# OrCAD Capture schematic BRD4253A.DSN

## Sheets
1 02: RF, Antenna & Power: size A3; title: EFR32FG12 Dual Band 2400/915 MHz Radio Board; rev: A02; note: BRD4253A; note: TAB
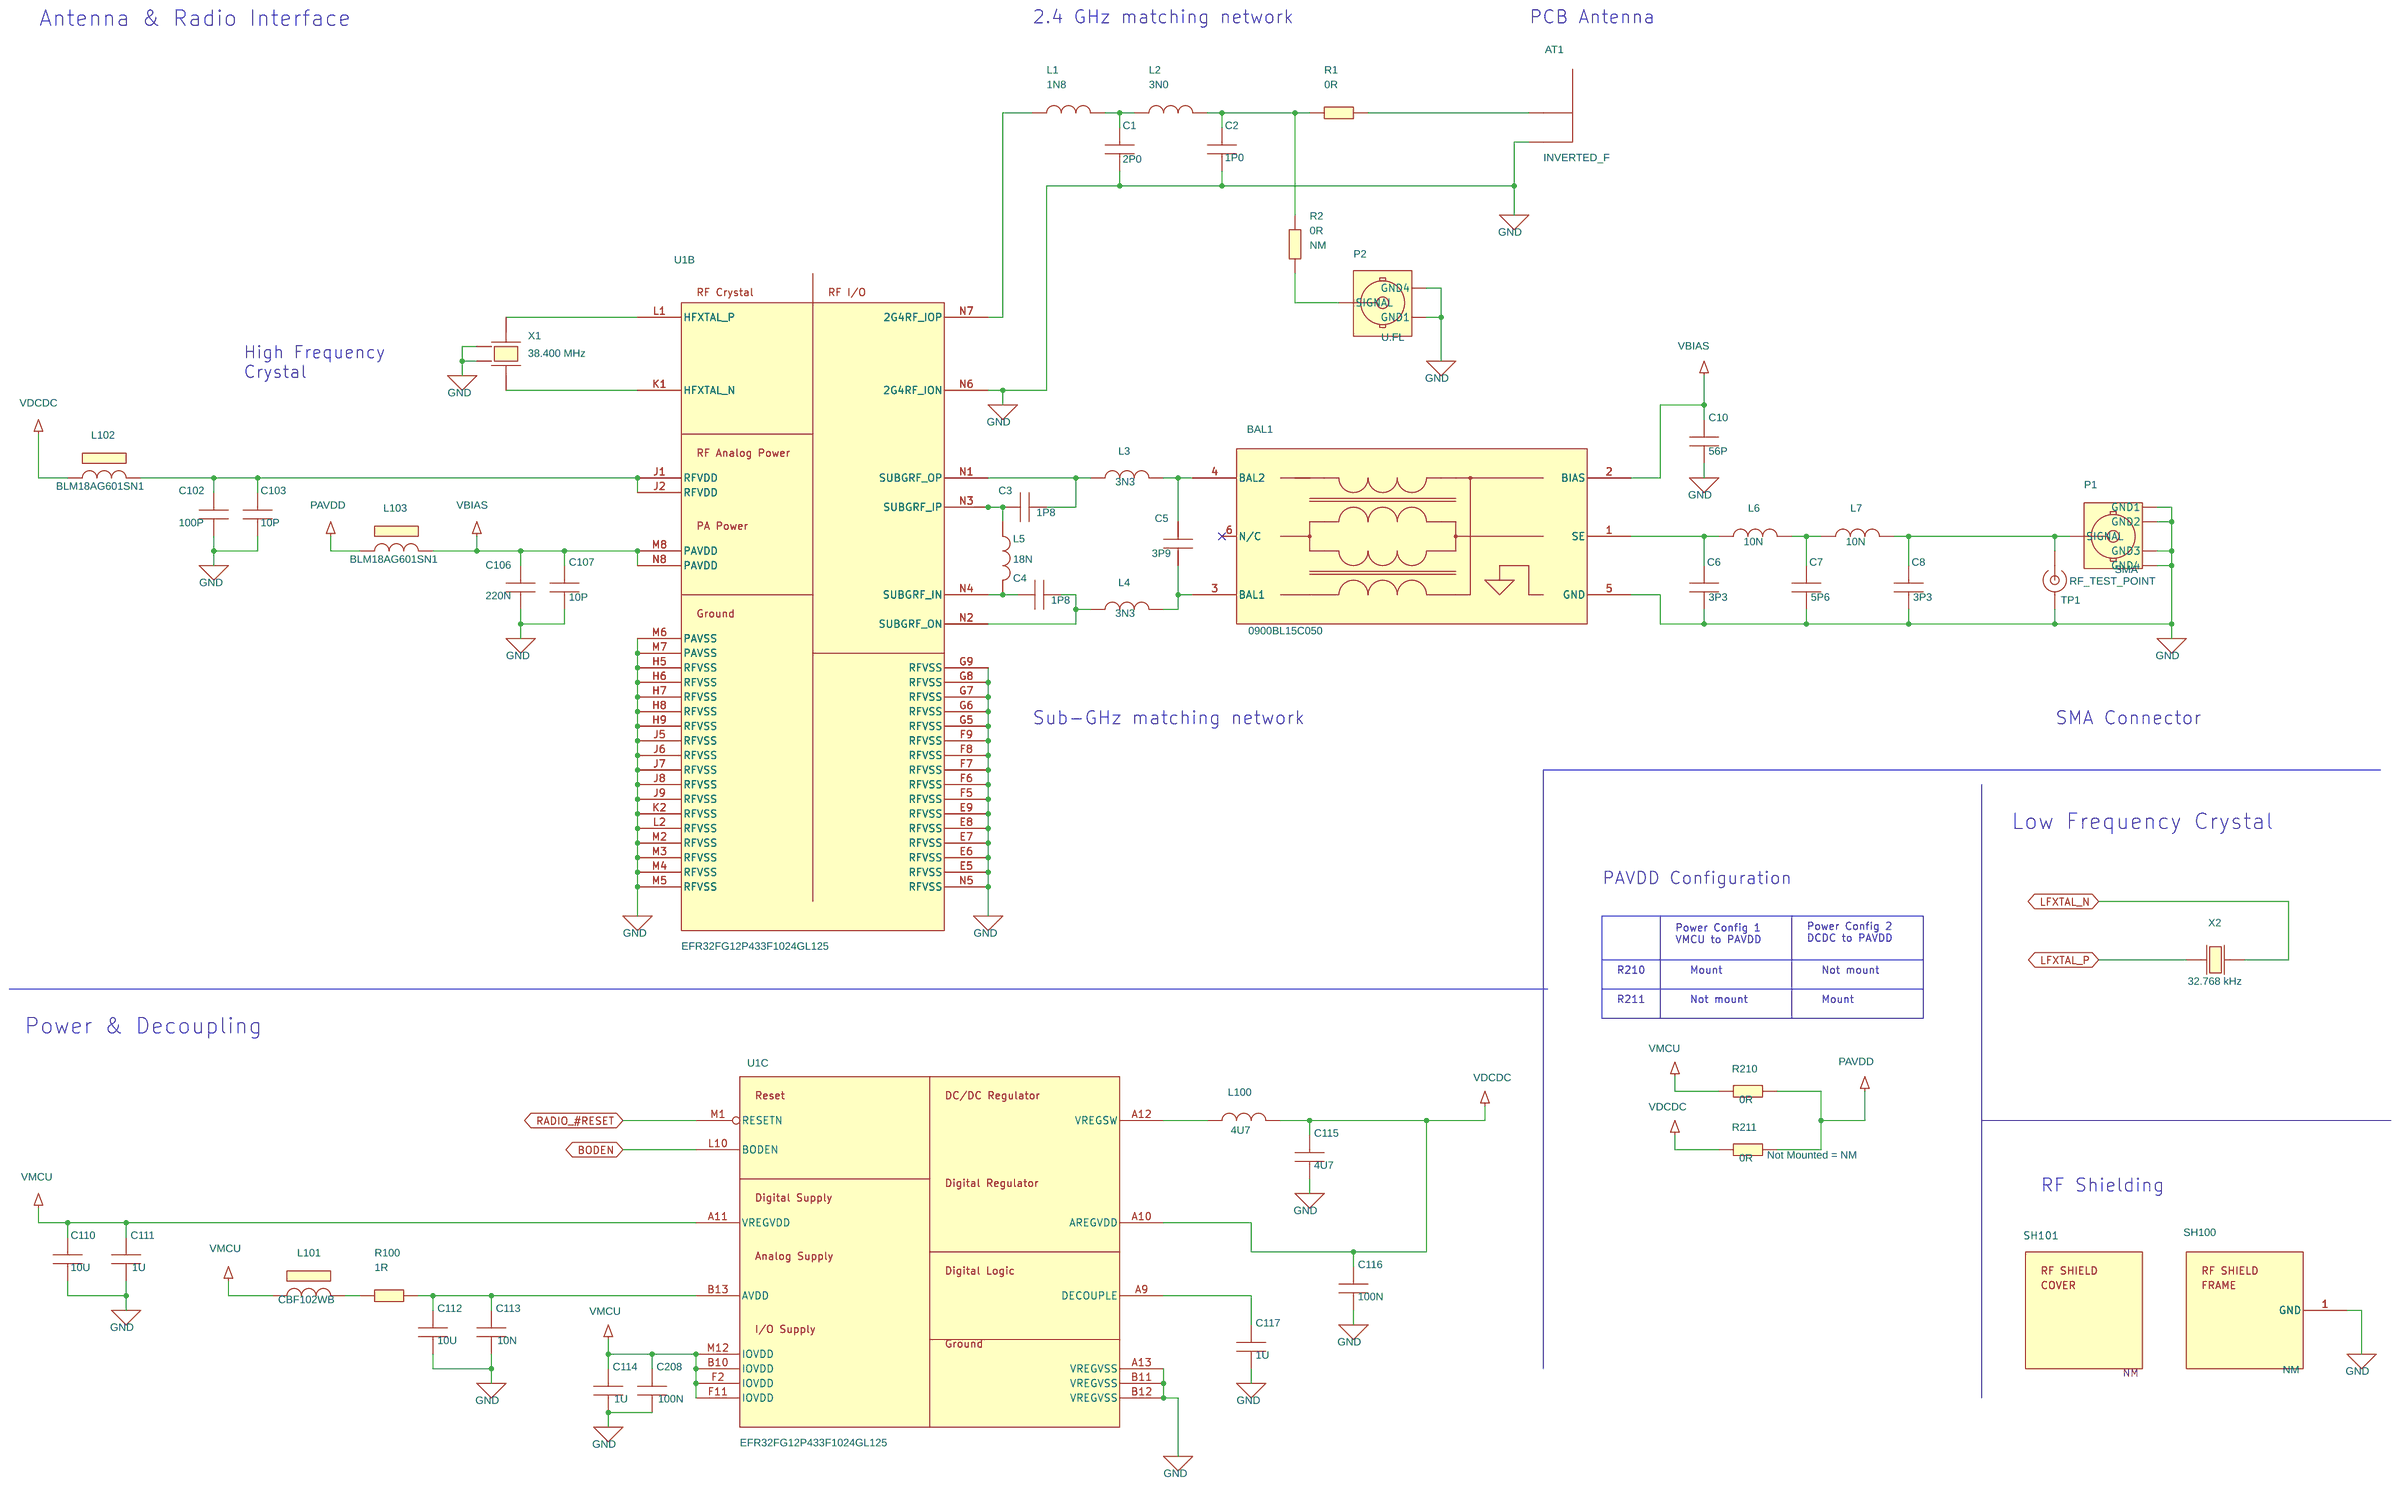
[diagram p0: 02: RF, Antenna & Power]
2 01: Title Page: company: Silicon Labs; note: JSH; note: JNO
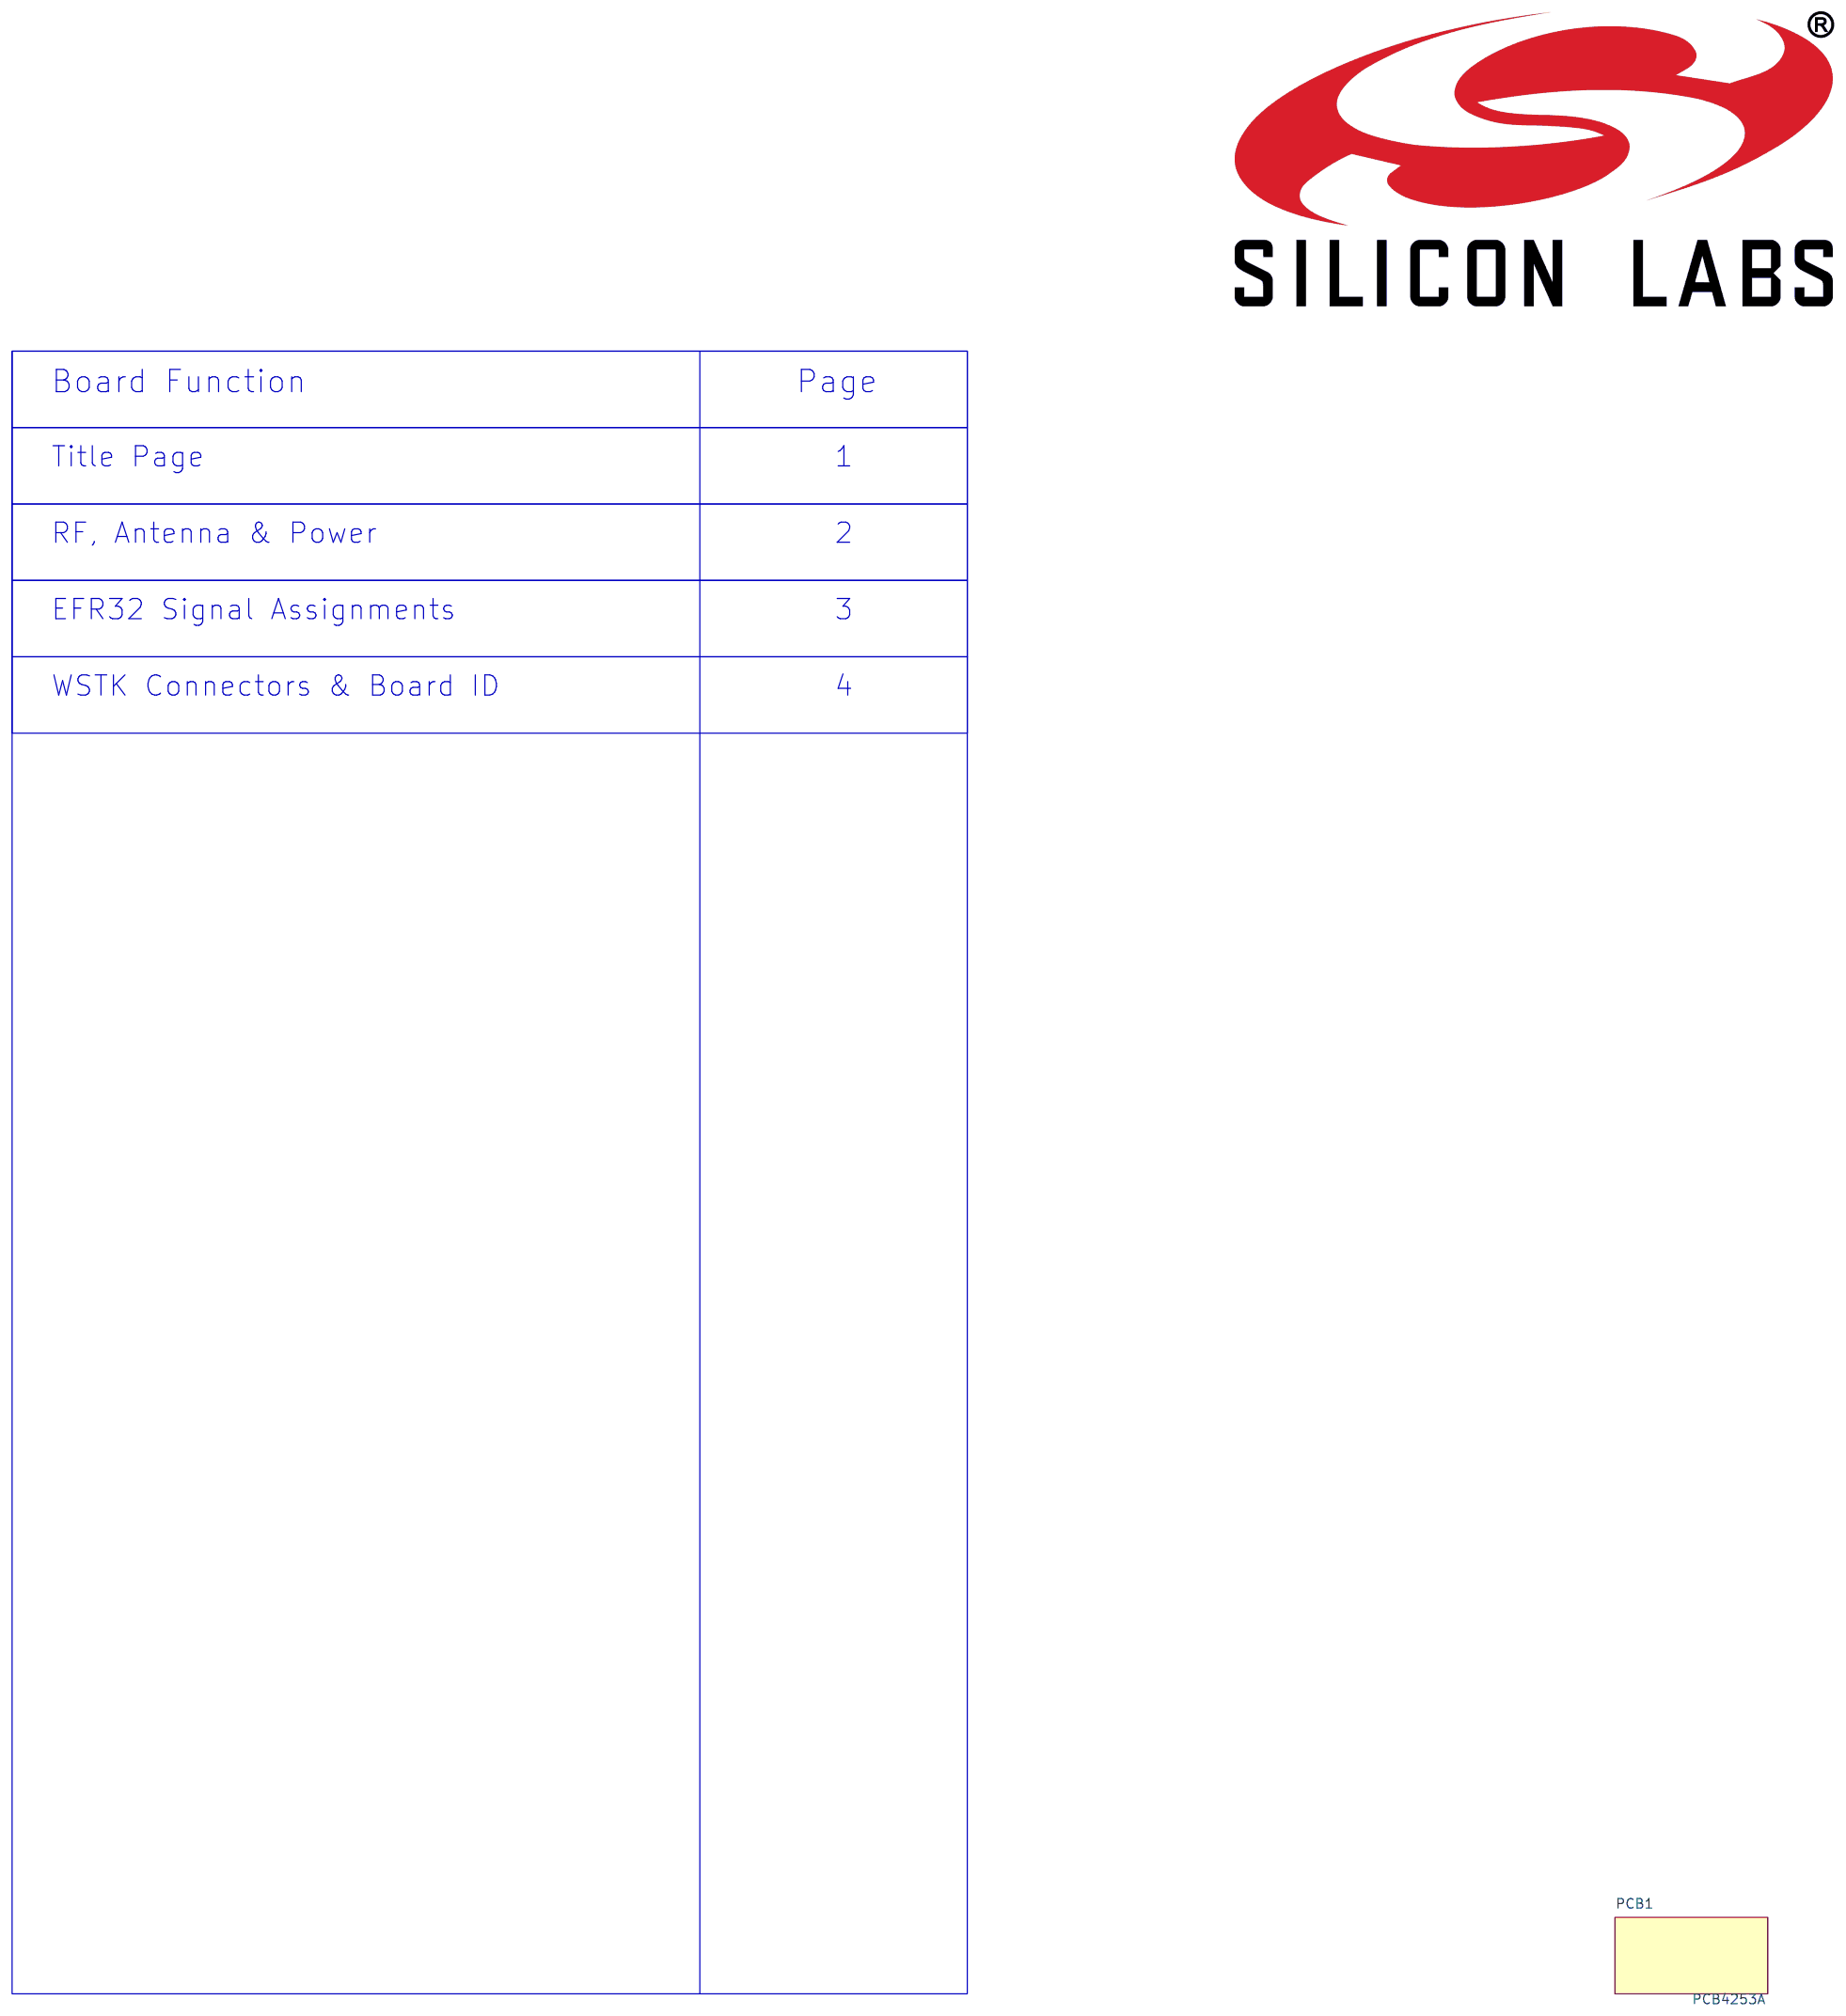
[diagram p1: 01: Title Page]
3 03: EFR32 Signal Assignments: size A3
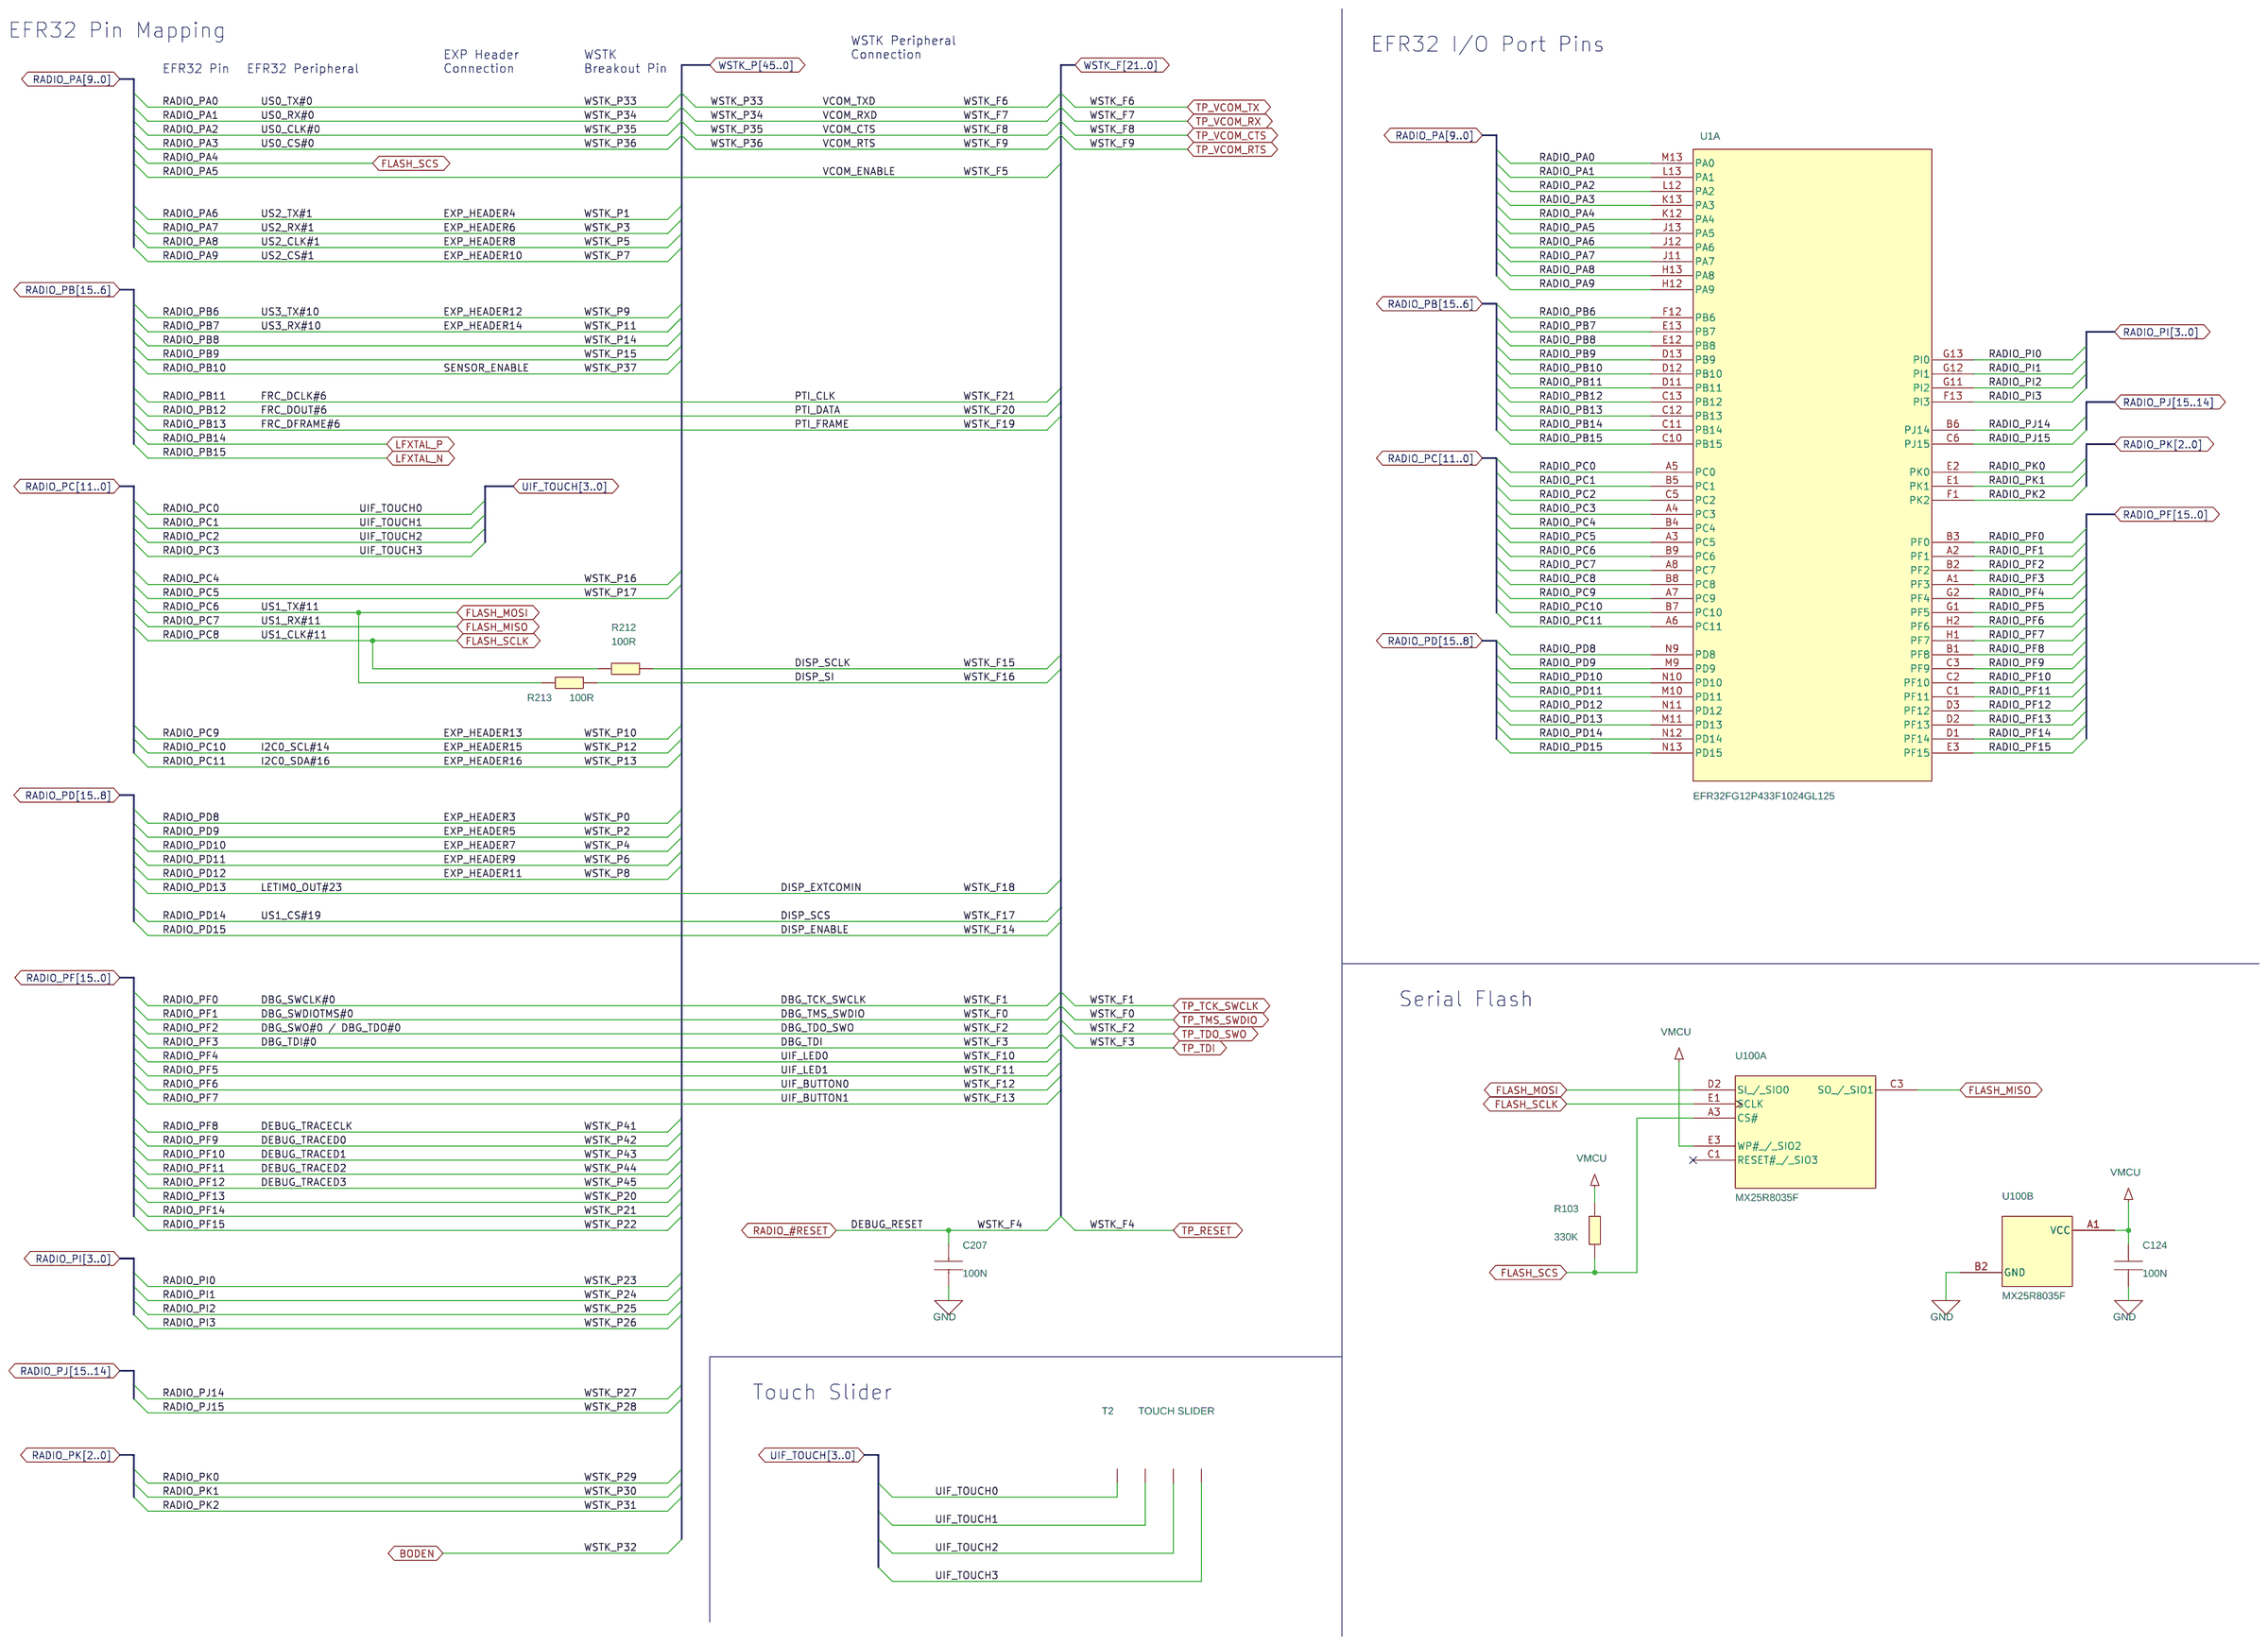
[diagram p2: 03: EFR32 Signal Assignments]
4 04: WSTK Connectors & Board ID: size A3
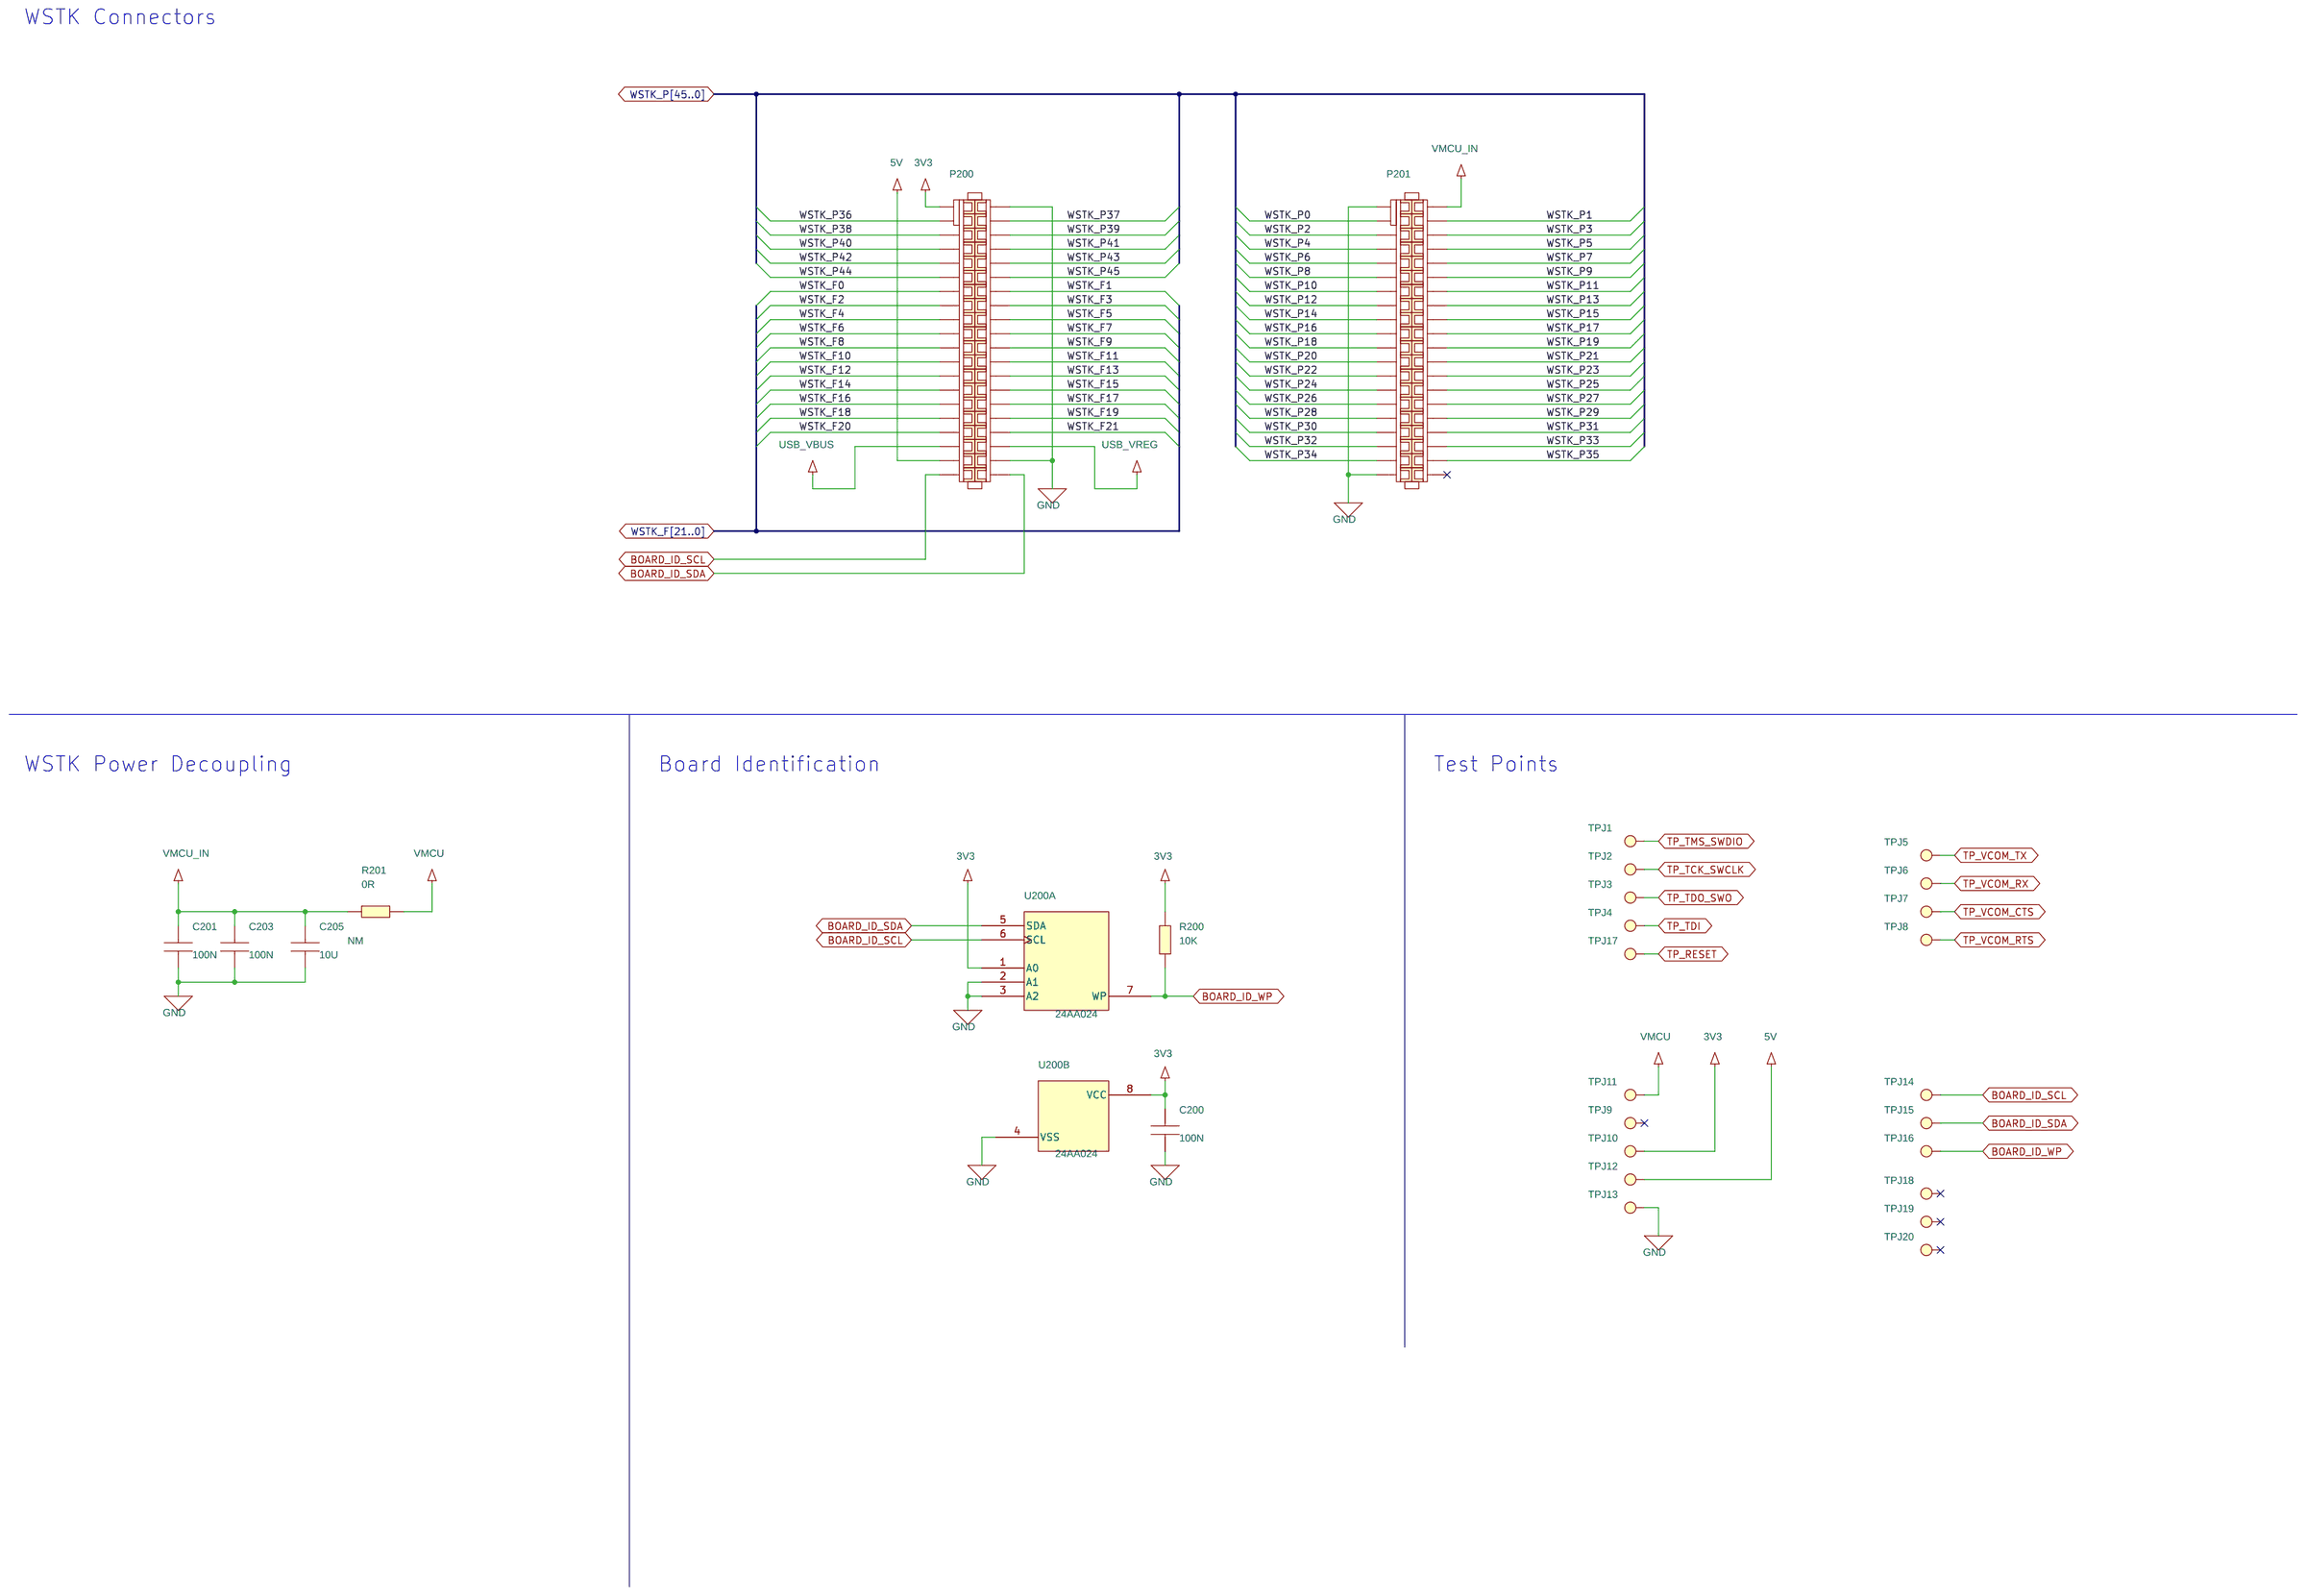
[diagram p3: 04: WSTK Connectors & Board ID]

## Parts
sheet 01: Title Page
PCB1  PCB4253A  [N/A]
sheet 02: RF, Antenna & Power
AT1  INVERTED_F  [ANT_INV_F_2.4_GHZ_17.3MM_MIR]
BAL1  0900BL15C050  [BALUN_JOH_0900BL15]
C1  2P0  [C0402_L]
C2  1P0  [C0402_L]
C3  1P8  [C0402_L]
C4  1P8  [C0402_L]
C5  3P9  [T_0402]
C6  3P3  [C0402_L]
C7  5P6  [C0402_L]
C8  3P3  [C0402_L]
C10  56P  [C0402_L]
C102  100P  [C0402_L]
C103  10P  [C0402_L]
C106  220N  [C0402_L]
C107  10P  [C0402_L]
C110  10U  [C0603_L]
C111  1U  [C0402_L]
C112  10U  [C0603_L]
C113  10N  [C0402_L]
C114  1U  [C0402_L]
C115  4U7  [C0402_L]
C116  100N  [C0402_L]
C117  1U  [C0402_L]
C208  100N  [C0402_L]
L1  1N8  [COIL_0402_L]
L2  3N0  [COIL_0402_L]
L3  3N3  [COIL_0402_L]
L4  3N3  [COIL_0402_L]
L5  18N  [COIL_0402_L]
L6  10N  [COIL_0402_L]
L7  10N  [COIL_0402_L]
L100  4U7  [COIL_MUR_LQH3NP_1212]
L101  CBF102WB  [COIL_WURTH_CBF_0603_L]
L102  BLM18AG601SN1  [COIL_MUR_BLM18_0603]
L103  BLM18AG601SN1  [COIL_MUR_BLM18_0603]
P1  SMA  [TE_SMA_1814832_TH_VER]
P2  U.FL  [COAX_HIROSE_U.FL_CL331-0471]
R1  0R  [R0402_L]
R2  0R  [R0402_L]
R100  1R  [R0402_L]
R210  0R  [R0402_L]
R211  0R  [R0402_L]
SH100  RF_SHIELD_FRAME_BMI-S-203-F  [RF_SHIELD_FRAME_BMI-S-203-F_PCB4100]
SH101  RF_SHIELD_COVER_BMI-S-203-C
TP1  RF_TEST_POINT  [TP_INGUN_50_OHM_CLOSED]
U1  EFR32FG12P433F1024GL125  (sections A,B,C)
X1  38.400 MHz  [X_SSS_DSX211SH_2.05X1.65-4]
X2  32.768 kHz  [X_MCS_CM8V-T1A]
sheet 03: EFR32 Signal Assignments
C124  100N  [C0402_L]
C207  100N  [C0402_L]
R103  330K  [R0402_L]
R212  100R  [R0402_L]
R213  100R  [R0402_L]
T2  TOUCH SLIDER  [TOUCH_SLIDER2_28.0X7.0-4]
U100  MX25R8035F  [BGA8_M040_1.24x1.75_WLCSP]  (sections A,B)
sheet 04: WSTK Connectors & Board ID
C200  100N  [C0402_L]
C201  100N  [C0402_L]
C203  100N  [C0402_L]
C205  10U  [C0805_L]
P200  SOCKET_2X20_1.27MM_SMD  [SAM_SFC-120-T2-D-A-2X20_SNUM]
P201  SOCKET_2X20_1.27MM_SMD  [SAM_SFC-120-T2-D-A-2X20_SNUM]
R200  10K  [T_0402]
R201  0R  [R0402_L]
TPJ1  TPJ_SMD  [TP_1.0_SMD]
TPJ2  TPJ_SMD  [TP_1.0_SMD]
TPJ3  TPJ_SMD  [TP_1.0_SMD]
TPJ4  TPJ_SMD  [TP_1.0_SMD]
TPJ5  TPJ_SMD  [TP_1.0_SMD]
TPJ6  TPJ_SMD  [TP_1.0_SMD]
TPJ7  TPJ_SMD  [TP_1.0_SMD]
TPJ8  TPJ_SMD  [TP_1.0_SMD]
TPJ9  TPJ_SMD  [TP_1.0_SMD]
TPJ10  TPJ_SMD  [TP_1.0_SMD]
TPJ11  TPJ_SMD  [TP_1.0_SMD]
TPJ12  TPJ_SMD  [TP_1.0_SMD]
TPJ13  TPJ_SMD  [TP_1.0_SMD]
TPJ14  TPJ_SMD  [TP_1.0_SMD]
TPJ15  TPJ_SMD  [TP_1.0_SMD]
TPJ16  TPJ_SMD  [TP_1.0_SMD]
TPJ17  TPJ_SMD  [TP_1.0_SMD]
TPJ18  TPJ_SMD  [TP_1.0_SMD]
TPJ19  TPJ_SMD  [TP_1.0_SMD]
TPJ20  TPJ_SMD  [TP_1.0_SMD]
U200  24AA024  [TDFN8_M050_2.0X3.0_EP]  (sections A,B)

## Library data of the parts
PCB1 = PCB: Mfg #: PCB4253A Rev. A01
AT1 = ANT_INVERTED_F
BAL1 = 0900BL15C050: Mfg: Johanson Technology
C1 = C0402: Mfg: Murata; Mfg #: GRM1555C1H2R0WA01D; Technology: C0G; Tolerance: ±0.05P
C2 = C0402: Mfg: Murata; Mfg #: GRM1555C1H1R0WA01D; Technology: C0G; Tolerance: ±0.05P
C3 C4 = C0402: Mfg: Murata; Mfg #: GRM1555C1H1R8WA01D; Technology: C0G; Tolerance: ±0.05pF
C5 = C0402: Mfg: Murata; Mfg #: GRM1555C1H3R9WA01D; Technology: C0G; Tolerance: ±0.05pF
C6 C8 = C0402: Mfg: Murata; Mfg #: GRM1555C1H3R3BA01D; Technology: C0G; Tolerance: ±0.1pF
C7 = C0402: Mfg: Murata; Mfg #: GRM1555C1H5R6BA01D; Technology: C0G; Tolerance: ±0.1pF
C10 = C0402: Mfg: Murata; Mfg #: GRM1555C1H560GA01D; Technology: C0G; Tolerance: ±2%
C102 C103 C107 = C0402: Rating: 50V; Technology: C0G; Tolerance: 5%
C106 C113 C116 C124 C200 C201 C203 C207 = C0402: Rating: 16V; Technology: X7R; Tolerance: 10%
C110 C112 = C0603: Rating: 6.3V; Technology: X5R; Tolerance: 20%
C111 C114 C117 C208 = C0402: Rating: 25V; Technology: X5R; Tolerance: 10%
C115 = C0402: Rating: 6.3V; Technology: X5R; Tolerance: 10%
L1 = L0402: Mfg: Murata; Mfg #: LQP15MN1N8W02D; Tolerance: ±0.05N
L2 = L0402: Mfg: Murata; Mfg #: LQP15MN3N0W02D; Tolerance: ±0.05N
L3 L4 = L0402: Mfg: Murata; Mfg #: LQW15AN3N3B80D; Tolerance: ±0.1nH
L5 = L0402: Mfg: Murata; Mfg #: LQW15AN18NG00D; Tolerance: ±2%
L6 L7 = L0402: Mfg: Murata; Mfg #: LQW15AN10NJ00D; Tolerance: ±5%
L100 = LQH3NP: Mfg #: LQH3NPN4R7MM0L
L101 = CBF102WB
L102 L103 = BLM18AG
P1 = SMA_TH
P2 = HIROSE_U.FL
R1 R100 R103 R200 R201 R210 R212 R213 = R0402
R2 R211 = R0402: Not Mounted: NM
SH100 = RF_SHIELD_FRAME_BMI-S-203-F: Not Mounted: NM
SH101 = RF_SHIELD_COVER_BMI-S-203-C: Not Mounted: NM
TP1 = TP_RF
U1 = EFR32MG2_BGA125_0A: Mfg #: EFR32FG12P433F1024GL125-BR
X1 = DSX211SH: Mfg: KDS; Mfg #: DSX211SH 1ZZNAE38400AB0A
X2 = CM8V-T1A: Mfg: KDS; Mfg #: DST210 1TJG125DP1A0012
T2 = TOUCH_SLIDER: CONTEC Footprint: TOUCH_SLIDER_28.0X7.0-4_L111
U100 = MX25R8035
C205 = C0805: Not Mounted: NM; Rating: 10V; Technology: X5R; Tolerance: 10%
P200 P201 = SOCKET_2X20_1.27MM_SMD
TPJ1-TPJ20 = TPJ_SMD
U200 = 24AA024

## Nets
3V3: C200.1 P200.1 R200.2 TPJ10.1(TP) U200.1(A0) U200.8(VCC)
5V: P200.37 TPJ12.1(TP)
GND: AT1.2(GND) BAL1.5(GND) C1.1 C2.1 C6.2 C7.2 C8.2 C10.2 C102.2 C103.2 C106.2 C107.2 C110.2 C111.2 C112.2 C113.2 C114.2 C115.2 C116.2 C117.2 C124.2 C200.2 C201.2 C203.2 C205.2 C207.2 C208.2 P1.2(GND1) P1.3(GND2) P1.4(GND3) P1.5(GND4) P2.2(GND1) P2.3(GND4) P200.2 P200.38 P201.1 P201.39 SH100.1(GND) TP1.2(GND) TPJ13.1(TP) U1.A13(VREGVSS) U1.B11(VREGVSS) U1.B12(VREGVSS) U1.E5(RFVSS) U1.E6(RFVSS) U1.E7(RFVSS) U1.E8(RFVSS) U1.E9(RFVSS) U1.F5(RFVSS) U1.F6(RFVSS) U1.F7(RFVSS) U1.F8(RFVSS) U1.F9(RFVSS) U1.G5(RFVSS) U1.G6(RFVSS) U1.G7(RFVSS) U1.G8(RFVSS) U1.G9(RFVSS) U1.H5(RFVSS) U1.H6(RFVSS) U1.H7(RFVSS) U1.H8(RFVSS) U1.H9(RFVSS) U1.J5(RFVSS) U1.J6(RFVSS) U1.J7(RFVSS) U1.J8(RFVSS) U1.J9(RFVSS) U1.K2(RFVSS) U1.L2(RFVSS) U1.M2(RFVSS) U1.M3(RFVSS) U1.M4(RFVSS) U1.M5(RFVSS) U1.M6(PAVSS) U1.M7(PAVSS) U1.N5(RFVSS) U1.N6(2G4RF_ION) U100.B2(GND) U200.2(A1) U200.3(A2) U200.4(VSS) X1.2 X1.4
BOARD_ID_SCL: P200.39 TPJ14.1(TP) U200.6(SCL)
BOARD_ID_SDA: P200.40 TPJ15.1(TP) U200.5(SDA)
BOARD_ID_WP: R200.1 TPJ16.1(TP) U200.7(WP)
BODEN: P201.35 U1.L10(BODEN)
FLASH_MISO: U1.A8(PC7) U100.C3(SO_/_SIO1)
FLASH_MOSI: R213.1 U1.B9(PC6) U100.D2(SI_/_SIO0)
FLASH_SCLK: R212.1 U1.B8(PC8) U100.E1(SCLK)
FLASH_SCS: R103.2 U1.K12(PA4) U100.A3(CS#)
LFXTAL_N: U1.C10(PB15) X2.1
LFXTAL_P: U1.C11(PB14) X2.2
PAVDD: L103.1 R210.1 R211.1
RADIO_#RESET: C207.1 P200.17 TPJ17.1(TP) U1.M1(RESETN)
RADIO_PA0: P200.19 P201.36 TPJ5.1(TP) U1.M13(PA0)
RADIO_PA1: P200.20 P201.37 TPJ6.1(TP) U1.L13(PA1)
RADIO_PA2: P200.21 P201.38 TPJ7.1(TP) U1.L12(PA2)
RADIO_PA3: P200.3 P200.22 TPJ8.1(TP) U1.K13(PA3)
RADIO_PA5: P200.18 U1.J13(PA5)
RADIO_PA6: P201.4 U1.J12(PA6)
RADIO_PA7: P201.6 U1.J11(PA7)
RADIO_PA8: P201.8 U1.H13(PA8)
RADIO_PA9: P201.10 U1.H12(PA9)
RADIO_PB6: P201.12 U1.F12(PB6)
RADIO_PB7: P201.14 U1.E13(PB7)
RADIO_PB8: P201.17 U1.E12(PB8)
RADIO_PB9: P201.18 U1.D13(PB9)
RADIO_PB10: P200.4 U1.D12(PB10)
RADIO_PB11: P200.34 U1.D11(PB11)
RADIO_PB12: P200.33 U1.C13(PB12)
RADIO_PB13: P200.32 U1.C12(PB13)
RADIO_PC0: T2.1(S1) U1.A5(PC0)
RADIO_PC1: T2.2(S2) U1.B5(PC1)
RADIO_PC2: T2.3(S3) U1.C5(PC2)
RADIO_PC3: T2.4(S4) U1.A4(PC3)
RADIO_PC4: P201.19 U1.B4(PC4)
RADIO_PC5: P201.20 U1.A3(PC5)
RADIO_PC9: P201.13 U1.A7(PC9)
RADIO_PC10: P201.15 U1.B7(PC10)
RADIO_PC11: P201.16 U1.A6(PC11)
RADIO_PD8: P201.3 U1.N9(PD8)
RADIO_PD9: P201.5 U1.M9(PD9)
RADIO_PD10: P201.7 U1.N10(PD10)
RADIO_PD11: P201.9 U1.M10(PD11)
RADIO_PD12: P201.11 U1.N11(PD12)
RADIO_PD13: P200.31 U1.M11(PD13)
RADIO_PD14: P200.30 U1.N12(PD14)
RADIO_PD15: P200.27 U1.N13(PD15)
RADIO_PF0: P200.14 TPJ2.1(TP) U1.B3(PF0)
RADIO_PF1: P200.13 TPJ1.1(TP) U1.A2(PF1)
RADIO_PF2: P200.15 TPJ3.1(TP) U1.B2(PF2)
RADIO_PF3: P200.16 TPJ4.1(TP) U1.A1(PF3)
RADIO_PF4: P200.23 U1.G2(PF4)
RADIO_PF5: P200.24 U1.G1(PF5)
RADIO_PF6: P200.25 U1.H2(PF6)
RADIO_PF7: P200.26 U1.H1(PF7)
RADIO_PF8: P200.8 U1.B1(PF8)
RADIO_PF9: P200.9 U1.C3(PF9)
RADIO_PF10: P200.10 U1.C2(PF10)
RADIO_PF11: P200.11 U1.C1(PF11)
RADIO_PF12: P200.12 U1.D3(PF12)
RADIO_PF13: P201.23 U1.D2(PF13)
RADIO_PF14: P201.24 U1.D1(PF14)
RADIO_PF15: P201.25 U1.E3(PF15)
RADIO_PI0: P201.26 U1.G13(PI0)
RADIO_PI1: P201.27 U1.G12(PI1)
RADIO_PI2: P201.28 U1.G11(PI2)
RADIO_PI3: P201.29 U1.F13(PI3)
RADIO_PJ14: P201.30 U1.B6(PJ14)
RADIO_PJ15: P201.31 U1.C6(PJ15)
RADIO_PK0: P201.32 U1.E2(PK0)
RADIO_PK1: P201.33 U1.E1(PK1)
RADIO_PK2: P201.34 U1.F1(PK2)
USB_VBUS: P200.35
USB_VREG: P200.36
VBIAS: BAL1.2(BIAS) C10.1 C106.1 C107.1 L103.2 U1.M8(PAVDD) U1.N8(PAVDD)
VDCDC: C115.1 C116.1 L100.2 L102.1 R211.2 U1.A10(AREGVDD)
VMCU: C110.1 C111.1 C114.1 C124.1 C208.1 L101.1 R103.1 R201.2 R210.2 TPJ11.1(TP) U1.A11(VREGVDD) U1.B10(IOVDD) U1.F2(IOVDD) U1.F11(IOVDD) U1.M12(IOVDD) U100.A1(VCC) U100.E3(WP#_/_SIO2)
VMCU_IN: C201.1 C203.1 C205.1 P201.2 R201.1
WSTK_F15: P200.28 R212.2
WSTK_F16: P200.29 R213.2
WSTK_P18: P201.21
WSTK_P19: P201.22
WSTK_P38: P200.5
WSTK_P39: P200.6
WSTK_P40: P200.7
N17603239: L1.1 U1.N7(2G4RF_IOP)
N17603622: U1.K1(HFXTAL_N) X1.1
N17603629: U1.L1(HFXTAL_P) X1.3
N17633617: C3.2 L5.2 U1.N3(SUBGRF_IP)
N17633620: C4.2 L5.1 U1.N4(SUBGRF_IN)
N17635927: C3.1 L3.2 U1.N1(SUBGRF_OP)
N17635932: C4.1 L4.2 U1.N2(SUBGRF_ON)
N17636016: BAL1.4(BAL2) C5.1 L3.1
N17636021: BAL1.3(BAL1) C5.2 L4.1
N17636973: C8.1 L7.1 P1.1(SIGNAL) TP1.1(RF)
N17636997: C7.1 L6.1 L7.2
N17637007: BAL1.1(SE) C6.1 L6.2
N17769146: C117.1 U1.A9(DECOUPLE)
N17769405: L100.1 U1.A12(VREGSW)
N17853356: C102.1 C103.1 L102.2 U1.J1(RFVDD) U1.J2(RFVDD)
N17855293: C2.2 L2.2 R1.1 R2.1
N17855333: P2.1(SIGNAL) R2.2
N17855346: AT1.1(ANT) R1.2
N17855379: C1.2 L1.2 L2.1
N17857389: L101.2 R100.1
N17857391: C112.1 C113.1 R100.2 U1.B13(AVDD)

Not connected (* = marked no-connect by the designer): BAL1 6(N/C)*; P201 40*; TPJ9 1(TP)*; TPJ18 1(TP)*; TPJ19 1(TP)*; TPJ20 1(TP)*; U100 C1(RESET#_/_SIO3)*

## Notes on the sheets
sheet 1
- Antenna & Radio Interface
- 2.4 GHz matching network
- PCB Antenna
- High Frequency
  Crystal
- Sub-GHz matching network
- SMA Connector
- Low Frequency Crystal
- PAVDD Configuration
- Power Config 1
  VMCU to PAVDD
- Power Config 2
  DCDC to PAVDD
- R210
- Mount
- Not mount
- R211
- Not mount
- Mount
- Power & Decoupling
- RF Shielding
sheet 2
- Board Function
- Page
- Title Page
- 1
- RF, Antenna & Power
- 2
- EFR32 Signal Assignments
- 3
- WSTK Connectors & Board ID
- 4
sheet 3
- EFR32 Pin Mapping
- WSTK Peripheral
  Connection
- EFR32 I/O Port Pins
- EFR32 Pin
- EFR32 Peripheral
- EXP Header
  Connection
- WSTK
  Breakout Pin
- Serial Flash
- Touch Slider
sheet 4
- WSTK Connectors
- WSTK Power Decoupling
- Board Identification
- Test Points
